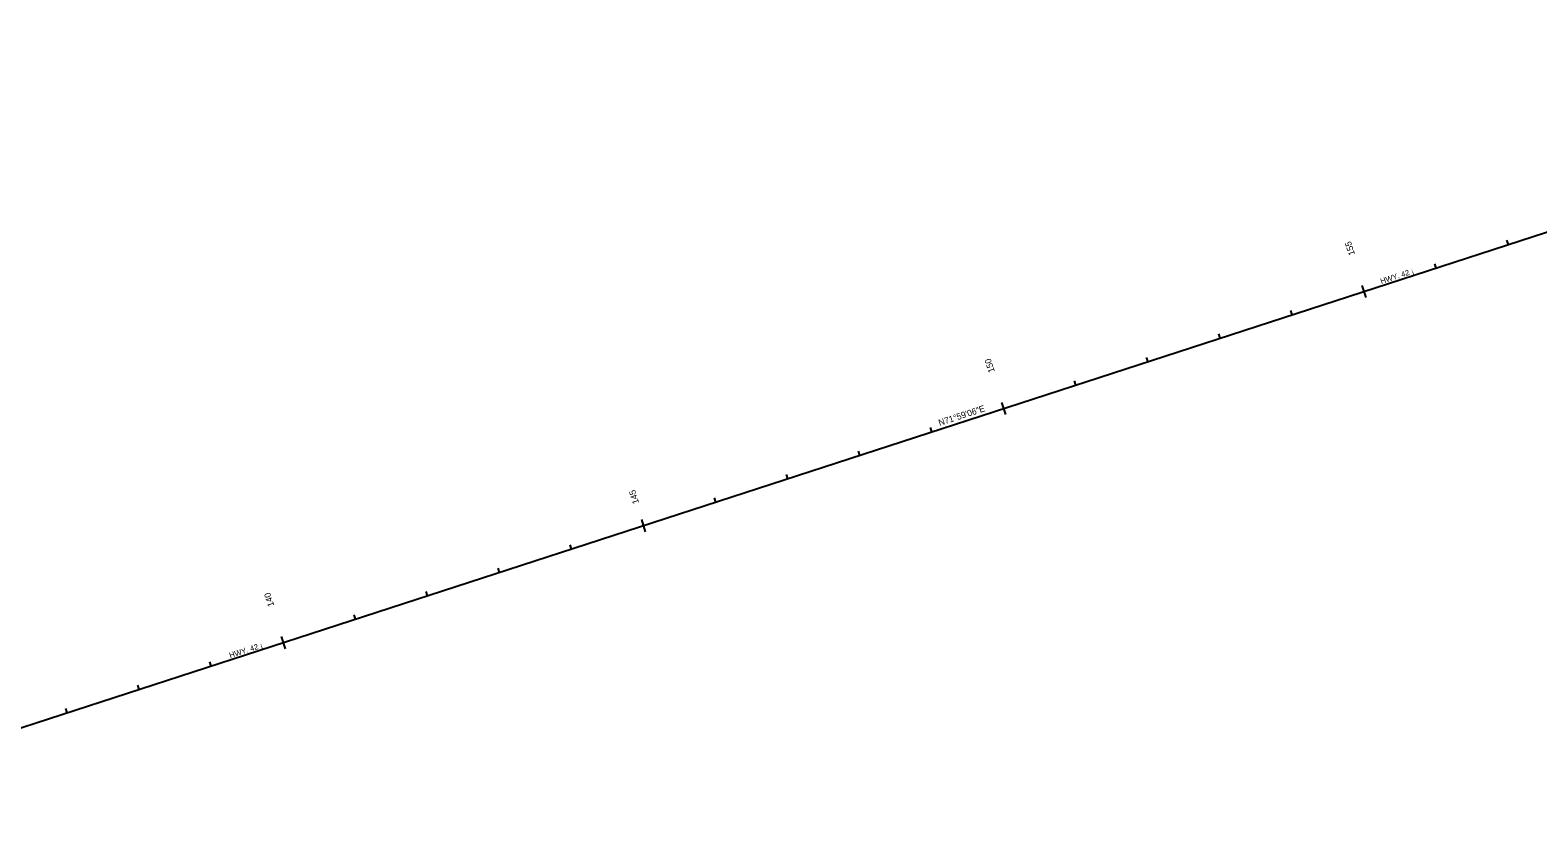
# Model space of a CAD drawing. Extents: x 1707563 to 1725852, y 372271 to 382824.
# Drawn here: x 1716733 to 1718723, y 376425 to 377457 of the extents above; entities that cross this region are included whole.
import ezdxf

# ---------------------------------------------------------------- set-up
doc = ezdxf.new("R2010")
doc.units = 0
for name, color, linetype in [('Default', 7, 'Continuous'), ('DSN_ROW_Line', 7, 'Continuous'), ('DSN_ROW_Point-Annotation', 7, 'Continuous'), ('DSN_ROW_Temp-Esmnt', 7, 'Continuous')]:
    doc.layers.add(name, color=color, linetype=linetype)

msp = doc.modelspace()

# ---------------------------------------------------------------- linework, layer by layer
at = {"layer": 'Default'}
msp.add_line((1716380, 376424.9), (1719554.6, 377457.3), dxfattribs=at)
at = {"layer": 'DSN_ROW_Line'}
msp.add_circle((1717967.3, 376941.1), 0.05, dxfattribs=at)
at = {"layer": 'DSN_ROW_Point-Annotation'}
for p, q in [((1718681.7, 377179.7), (1718683.6, 377174)), ((1718586.6, 377148.8), (1718588.5, 377143.1)), ((1718490.8, 377120.2), (1718496, 377104.2)), ((1718396.4, 377087), (1718398.3, 377081.3)), ((1718301.3, 377056), (1718303.2, 377050.3)), ((1718206.2, 377025.1), (1718208.1, 377019.4)), ((1718111.1, 376994.2), (1718113, 376988.5)), ((1718015.3, 376965.5), (1718020.5, 376949.6)), ((1717921, 376932.3), (1717922.8, 376926.6)), ((1717825.9, 376901.4), (1717827.7, 376895.7)), ((1717730.8, 376870.5), (1717732.6, 376864.8)), ((1717635.7, 376839.6), (1717637.5, 376833.9)), ((1717539.8, 376810.9), (1717545, 376794.9)), ((1717445.5, 376777.7), (1717447.3, 376772)), ((1717350.4, 376746.8), (1717352.2, 376741.1)), ((1717255.3, 376715.9), (1717257.1, 376710.1)), ((1717160.2, 376684.9), (1717162, 376679.2)), ((1717064.3, 376656.3), (1717069.5, 376640.3)), ((1716970, 376623.1), (1716971.8, 376617.4)), ((1716874.9, 376592.1), (1716876.7, 376586.4)), ((1716779.8, 376561.2), (1716781.6, 376555.5))]:
    msp.add_line(p, q, dxfattribs=at)
at = {"layer": 'DSN_ROW_Temp-Esmnt'}
msp.add_line((1716380, 376424.9), (1719554.6, 377457.3), dxfattribs=at)

# ---------------------------------------------------------------- texts
at = {"layer": 'Default'}
for p in [(1718516.5, 377122), (1716997.2, 376627.9)]:
    msp.add_text('HWY. 42 ¡', height=7.2, rotation=18.0149, dxfattribs=at).set_placement(p)
at = {"layer": 'DSN_ROW_Point-Annotation'}
for s, rotation, p in [('155', 108.0149, (1718481.8, 377161.4)), ('150', 108.0149, (1718006.4, 377006.6)), ('N71°59\'06"E', 18.0149, (1717933.5, 376934.5)), ('145', 108.0149, (1717537, 376833.1)), ('140', 108.0149, (1717055.4, 376697.4))]:
    msp.add_text(s, height=8.4, rotation=rotation, dxfattribs=at).set_placement(p)

doc.saveas('drawing.dxf')
